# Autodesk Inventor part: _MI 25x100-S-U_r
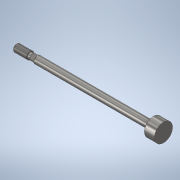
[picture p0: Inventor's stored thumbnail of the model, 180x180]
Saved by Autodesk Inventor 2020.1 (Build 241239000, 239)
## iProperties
Created: 2020-04
Part Number: _MI 25x100-S-U_r
Material: Steel, Carbon
Document SubType Name: Modeling
Designer: Safarabadi
Density: 7.85 g/cm^3
Appearance: Semi-Polished
Author: Safarabadi
Revision Number: NONE
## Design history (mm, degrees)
feature "_MI 25x100-S-U_r"
thread "Thread1" dims "d0" = 17.78, "d1" = 0
body "Solid1"
